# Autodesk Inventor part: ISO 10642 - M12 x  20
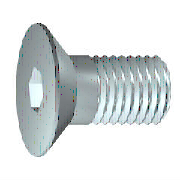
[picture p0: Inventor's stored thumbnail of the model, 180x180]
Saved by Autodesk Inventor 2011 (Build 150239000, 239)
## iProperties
IsCustomPart: 0
Created: 2010-02
Part Number: ISO 10642 - M12 x  20
Material: Steel
Description: Hexagon Socket Countersunk Head Screw-1 - Product grade A
Document SubType Name: Modeling
Standard: ISO 10642
Designer: 129877
Standard Revision: Second edition 2004-03-01
Standards Organization: ISO
Language: en-US
Size Designation: M12 x  20
Categories: <MemberInstance><Categories><Category DisplayName="Fasteners" InternalName="e4da775c-781d-43d5-af7c-5136215cf5a6" Mnemonic="FSTN"><Category DisplayName="Bolts"
Density: 7.85 g/cm^3
Mass: 25.3968 g
Surface Area: 17.1045 cm^2
Volume: 3.23526 cm^3
Author: 129877
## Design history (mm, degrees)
body "Solid1"
workplane "Work Plane1"
revolve "Body" stored, may be unused: angle "d13" = 90 deg
sketch "Sketch2"
  geometry: L1 (0, -16.184)-(0, 16.184) reference; L2 (-16.184, 0)-(16.184, 0) reference; L3 (4.619, 0)-(2.309, -4); L4 (2.309, -4)-(-2.309, -4); L5 (-2.309, -4)-(-4.619, 0); L6 (-4.619, 0)-(-2.309, 4); L7 (-2.309, 4)-(2.309, 4); L8 (2.309, 4)-(4.619, 0); A1 r 4.619 centre (0, 0) between (0, 4.619) and (4.619, 0) reference; 2 further points
  constraints: 12 end point, 2 coincident, 2 point on circle, 2 point on line, 12 other
extrude "Slot" join sketch "Sketch2" taper "d14" = 0 deg; stored distance "d30" = 10
feature "Thread" dims "d15" = 6.5 (= GEL), "d16" = 0
chamfer "Chamfer1" distance "d17" = 1.07354 (= -0.5 x SPD + 0.5 x GD); stored, may be unused: second distance "d18" = 1.07354 (= GUL), angle "d39" = 45 deg
sketch "Sketch1"
  geometry: L1 (20, 0)-(20, 6); L2 (20, 6)-(13.5, 6); L3 (13.5, 6)-(12.426, 6); L4 (0, 11.56)-(0, 4.619); L5 (0, 4.619)-(5.19, 4.619); L6 (5.19, 4.619)-(7.857, 0); L7 (7.857, 0)-(20, 0); L8 (0, 11.56)-(1.88, 11.56); L9 (1.88, 11.56)-(7.44, 6); L10 (12.426, 6)-(7.44, 6); L11 (13.5, 6)-(7.44, 6); L12 (7.44, 6)-(7.44, 6); L13 (-4, 0)-(24, 0) reference; L14 (0, -2.312)-(0, 13.872) reference
  constraints: 24 end point, 4 collinear, 3 parallel
  dimensions: "d0" = 20 distance between parallel lines of L4 L1 (= NLG); "d1" = 6.5 distance from line of L2.end L1 (= GEL); "d2" = 5.19 distance from line of L5.end L4 (= INTI); "d3" = 12 diameter of L2 L7 (= GD); "d6" = 7.44 distance from line of L9.end L4 (= KOH); "d7" = 45 deg angle of L9 L7 (= 0.5 x SEWI); "d8" = 9.2376 diameter of L5 L7 (= 1.1547 x SW); "d9" = 60 deg angle of L6 L7; "d10" = 23.12 diameter of L8 L7 (= KOD); "d11" = 12 diameter of L10 L7 (= BDM); "d12" = 1.07354 distance of L3.end L2.end (= GAL)
other parameters: "NLG" = 20 [user parameter; used in 1 equation term], "INTI" = 5.19 [user parameter; used in 1 equation term], "GEL" = 6.5 [user parameter; used in 2 equation terms], "GAL" = 1.07354 (= 0.61345 x PTC) [user parameter; used in 1 equation term], "KOH" = 7.44 [user parameter; used in 1 equation term], "KOD" = 23.12 [user parameter; used in 1 equation term], "GUL" = 1.07354 (= 0.61345 x PTC) [user parameter; used in 1 equation term], "SPD" = 9.85293 (= NND - 1.2269 x PTC) [user parameter; used in 1 equation term], "BDM" = 12 (= NND) [user parameter; used in 1 equation term], "GD" = 12 (= NND) [user parameter; used in 2 equation terms], "SEWI" = 90 deg [user parameter; used in 1 equation term], "d20" = 0, "SW" = 8 [user parameter; used in 1 equation term], "d43" = 0, "d44" = 0, "TOA" = 30 deg [user parameter], "GD1" = 9.85293 (= THREADDIA - 1.2269 x PTC) [user parameter], "EPV" = 13.44 [user parameter], "THREADDIA" = 12 [user parameter; used in 1 equation term], "TPU" = 5.71429 (computed from PTC) [user parameter], "PTC" = 1.75 [user parameter; used in 5 equation terms], "NND" = 12 [user parameter; used in 3 equation terms], "E0" = 9.24 [user parameter], "THREADDESC" = 12.345 [user parameter]
